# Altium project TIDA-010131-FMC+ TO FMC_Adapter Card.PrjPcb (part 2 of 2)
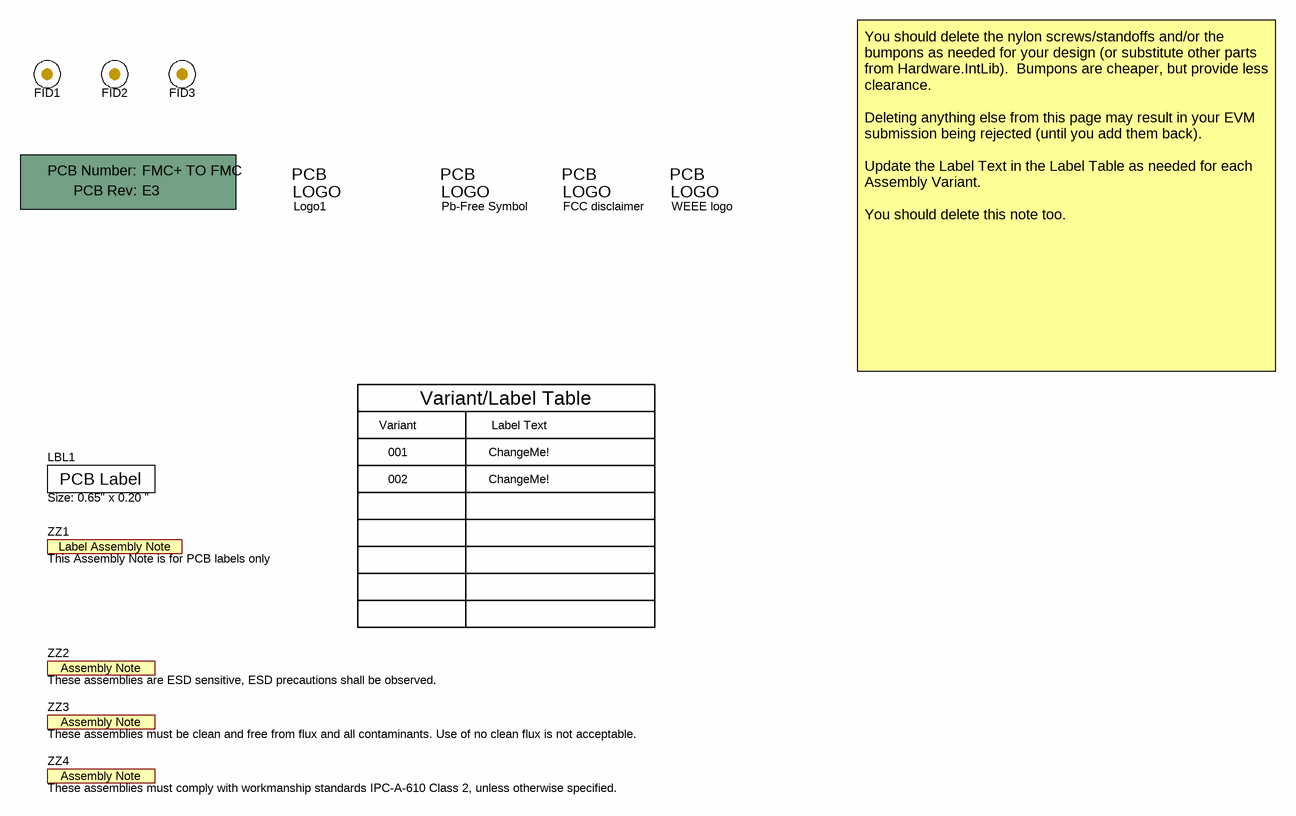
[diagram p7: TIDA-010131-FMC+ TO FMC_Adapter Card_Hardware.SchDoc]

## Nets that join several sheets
GND: TIDA-010131-FMC+ TO FMC_Adapter Card_Sheet1 (33 pins), TIDA-010131-FMC+ TO FMC_Adapter Card_Sheet2 (204 pins), TIDA-010131-FMC+ TO FMC_Adapter Card_Sheet3 (153 pins), TIDA-010131-FMC+ TO FMC_Adapter Card_Sheet4 (203 pins)
ADC_ALT_SYNC_N: TIDA-010131-FMC+ TO FMC_Adapter Card_Sheet2 (J1.H32), TIDA-010131-FMC+ TO FMC_Adapter Card_Sheet3 (R39.1 R45.2)
ADC_ALT_SYNC_P: TIDA-010131-FMC+ TO FMC_Adapter Card_Sheet1 (R27.1), TIDA-010131-FMC+ TO FMC_Adapter Card_Sheet2 (J1.H31), TIDA-010131-FMC+ TO FMC_Adapter Card_Sheet3 (R19.1)
ADC_DA0_N: TIDA-010131-FMC+ TO FMC_Adapter Card_Sheet2 (J1.C7), TIDA-010131-FMC+ TO FMC_Adapter Card_Sheet3 (J2.C7), TIDA-010131-FMC+ TO FMC_Adapter Card_Sheet4 (J4.C7)
ADC_DA0_P: TIDA-010131-FMC+ TO FMC_Adapter Card_Sheet2 (J1.C6), TIDA-010131-FMC+ TO FMC_Adapter Card_Sheet3 (J2.C6), TIDA-010131-FMC+ TO FMC_Adapter Card_Sheet4 (J4.C6)
ADC_DA1_N: TIDA-010131-FMC+ TO FMC_Adapter Card_Sheet2 (J1.A3), TIDA-010131-FMC+ TO FMC_Adapter Card_Sheet3 (J2.A3), TIDA-010131-FMC+ TO FMC_Adapter Card_Sheet4 (J4.A3)
ADC_DA1_P: TIDA-010131-FMC+ TO FMC_Adapter Card_Sheet2 (J1.A2), TIDA-010131-FMC+ TO FMC_Adapter Card_Sheet3 (J2.A2), TIDA-010131-FMC+ TO FMC_Adapter Card_Sheet4 (J4.A2)
ADC_DA2_N: TIDA-010131-FMC+ TO FMC_Adapter Card_Sheet2 (J1.A7), TIDA-010131-FMC+ TO FMC_Adapter Card_Sheet3 (J2.A7), TIDA-010131-FMC+ TO FMC_Adapter Card_Sheet4 (J4.A7)
ADC_DA2_P: TIDA-010131-FMC+ TO FMC_Adapter Card_Sheet2 (J1.A6), TIDA-010131-FMC+ TO FMC_Adapter Card_Sheet3 (J2.A6), TIDA-010131-FMC+ TO FMC_Adapter Card_Sheet4 (J4.A6)
ADC_DA3_N: TIDA-010131-FMC+ TO FMC_Adapter Card_Sheet2 (J1.A11), TIDA-010131-FMC+ TO FMC_Adapter Card_Sheet3 (J2.A11), TIDA-010131-FMC+ TO FMC_Adapter Card_Sheet4 (J4.A11)
ADC_DA3_P: TIDA-010131-FMC+ TO FMC_Adapter Card_Sheet2 (J1.A10), TIDA-010131-FMC+ TO FMC_Adapter Card_Sheet3 (J2.A10), TIDA-010131-FMC+ TO FMC_Adapter Card_Sheet4 (J4.A10)
ADC_DA4_N: TIDA-010131-FMC+ TO FMC_Adapter Card_Sheet2 (J1.A15), TIDA-010131-FMC+ TO FMC_Adapter Card_Sheet3 (J2.A15), TIDA-010131-FMC+ TO FMC_Adapter Card_Sheet4 (J4.A15)
ADC_DA4_P: TIDA-010131-FMC+ TO FMC_Adapter Card_Sheet2 (J1.A14), TIDA-010131-FMC+ TO FMC_Adapter Card_Sheet3 (J2.A14), TIDA-010131-FMC+ TO FMC_Adapter Card_Sheet4 (J4.A14)
ADC_DA5_N: TIDA-010131-FMC+ TO FMC_Adapter Card_Sheet2 (J1.A19), TIDA-010131-FMC+ TO FMC_Adapter Card_Sheet3 (J2.A19), TIDA-010131-FMC+ TO FMC_Adapter Card_Sheet4 (J4.A19)
ADC_DA5_P: TIDA-010131-FMC+ TO FMC_Adapter Card_Sheet2 (J1.A18), TIDA-010131-FMC+ TO FMC_Adapter Card_Sheet3 (J2.A18), TIDA-010131-FMC+ TO FMC_Adapter Card_Sheet4 (J4.A18)
ADC_DA6_N: TIDA-010131-FMC+ TO FMC_Adapter Card_Sheet2 (J1.B17), TIDA-010131-FMC+ TO FMC_Adapter Card_Sheet3 (J2.B17), TIDA-010131-FMC+ TO FMC_Adapter Card_Sheet4 (J4.B17)
ADC_DA6_P: TIDA-010131-FMC+ TO FMC_Adapter Card_Sheet2 (J1.B16), TIDA-010131-FMC+ TO FMC_Adapter Card_Sheet3 (J2.B16), TIDA-010131-FMC+ TO FMC_Adapter Card_Sheet4 (J4.B16)
ADC_DA7_N: TIDA-010131-FMC+ TO FMC_Adapter Card_Sheet2 (J1.B13), TIDA-010131-FMC+ TO FMC_Adapter Card_Sheet3 (J2.B13), TIDA-010131-FMC+ TO FMC_Adapter Card_Sheet4 (J4.B13)
ADC_DA7_P: TIDA-010131-FMC+ TO FMC_Adapter Card_Sheet2 (J1.B12), TIDA-010131-FMC+ TO FMC_Adapter Card_Sheet3 (J2.B12), TIDA-010131-FMC+ TO FMC_Adapter Card_Sheet4 (J4.B12)
ADC_DB0_N: TIDA-010131-FMC+ TO FMC_Adapter Card_Sheet2 (J1.B5), TIDA-010131-FMC+ TO FMC_Adapter Card_Sheet3 (J2.B5), TIDA-010131-FMC+ TO FMC_Adapter Card_Sheet4 (J4.B5)
ADC_DB0_P: TIDA-010131-FMC+ TO FMC_Adapter Card_Sheet2 (J1.B4), TIDA-010131-FMC+ TO FMC_Adapter Card_Sheet3 (J2.B4), TIDA-010131-FMC+ TO FMC_Adapter Card_Sheet4 (J4.B4)
ADC_DB1_N: TIDA-010131-FMC+ TO FMC_Adapter Card_Sheet2 (J1.B9), TIDA-010131-FMC+ TO FMC_Adapter Card_Sheet3 (J2.B9), TIDA-010131-FMC+ TO FMC_Adapter Card_Sheet4 (J4.B9)
ADC_DB1_P: TIDA-010131-FMC+ TO FMC_Adapter Card_Sheet2 (J1.B8), TIDA-010131-FMC+ TO FMC_Adapter Card_Sheet3 (J2.B8), TIDA-010131-FMC+ TO FMC_Adapter Card_Sheet4 (J4.B8)
ADC_DB2_N: TIDA-010131-FMC+ TO FMC_Adapter Card_Sheet2 (J1.Y11), TIDA-010131-FMC+ TO FMC_Adapter Card_Sheet4 (J4.Y11)
ADC_DB2_P: TIDA-010131-FMC+ TO FMC_Adapter Card_Sheet2 (J1.Y10), TIDA-010131-FMC+ TO FMC_Adapter Card_Sheet4 (J4.Y10)
ADC_DB3_N: TIDA-010131-FMC+ TO FMC_Adapter Card_Sheet2 (J1.Y15), TIDA-010131-FMC+ TO FMC_Adapter Card_Sheet4 (J4.Y15)
ADC_DB3_P: TIDA-010131-FMC+ TO FMC_Adapter Card_Sheet2 (J1.Y14), TIDA-010131-FMC+ TO FMC_Adapter Card_Sheet4 (J4.Y14)
ADC_DB4_N: TIDA-010131-FMC+ TO FMC_Adapter Card_Sheet2 (J1.Y19), TIDA-010131-FMC+ TO FMC_Adapter Card_Sheet4 (J4.Y19)
ADC_DB4_P: TIDA-010131-FMC+ TO FMC_Adapter Card_Sheet2 (J1.Y18), TIDA-010131-FMC+ TO FMC_Adapter Card_Sheet4 (J4.Y18)
ADC_DB5_N: TIDA-010131-FMC+ TO FMC_Adapter Card_Sheet2 (J1.Y23), TIDA-010131-FMC+ TO FMC_Adapter Card_Sheet4 (J4.Y23)
ADC_DB5_P: TIDA-010131-FMC+ TO FMC_Adapter Card_Sheet2 (J1.Y22), TIDA-010131-FMC+ TO FMC_Adapter Card_Sheet4 (J4.Y22)
ADC_DB6_N: TIDA-010131-FMC+ TO FMC_Adapter Card_Sheet2 (J1.Z13), TIDA-010131-FMC+ TO FMC_Adapter Card_Sheet4 (J4.Z13)
ADC_DB6_P: TIDA-010131-FMC+ TO FMC_Adapter Card_Sheet2 (J1.Z12), TIDA-010131-FMC+ TO FMC_Adapter Card_Sheet4 (J4.Z12)
ADC_DB7_N: TIDA-010131-FMC+ TO FMC_Adapter Card_Sheet2 (J1.Z17), TIDA-010131-FMC+ TO FMC_Adapter Card_Sheet4 (J4.Z17)
ADC_DB7_P: TIDA-010131-FMC+ TO FMC_Adapter Card_Sheet2 (J1.Z16), TIDA-010131-FMC+ TO FMC_Adapter Card_Sheet4 (J4.Z16)
ADC_SYNC_N: TIDA-010131-FMC+ TO FMC_Adapter Card_Sheet2 (R48.2), TIDA-010131-FMC+ TO FMC_Adapter Card_Sheet3 (J2.G13), TIDA-010131-FMC+ TO FMC_Adapter Card_Sheet4 (J4.G13)
ADC_SYNC_P: TIDA-010131-FMC+ TO FMC_Adapter Card_Sheet2 (R47.2), TIDA-010131-FMC+ TO FMC_Adapter Card_Sheet3 (J2.G12), TIDA-010131-FMC+ TO FMC_Adapter Card_Sheet4 (J4.G12)
C18: TIDA-010131-FMC+ TO FMC_Adapter Card_Sheet2 (J1.C18), TIDA-010131-FMC+ TO FMC_Adapter Card_Sheet3 (J2.C18), TIDA-010131-FMC+ TO FMC_Adapter Card_Sheet4 (J4.C18)
C34: TIDA-010131-FMC+ TO FMC_Adapter Card_Sheet2 (J1.C34), TIDA-010131-FMC+ TO FMC_Adapter Card_Sheet3 (J2.C34), TIDA-010131-FMC+ TO FMC_Adapter Card_Sheet4 (J4.C34)
C35: TIDA-010131-FMC+ TO FMC_Adapter Card_Sheet2 (J1.C35), TIDA-010131-FMC+ TO FMC_Adapter Card_Sheet3 (J2.C35), TIDA-010131-FMC+ TO FMC_Adapter Card_Sheet4 (J4.C35)
C37: TIDA-010131-FMC+ TO FMC_Adapter Card_Sheet2 (J1.C37), TIDA-010131-FMC+ TO FMC_Adapter Card_Sheet3 (J2.C37), TIDA-010131-FMC+ TO FMC_Adapter Card_Sheet4 (J4.C37)
C39: TIDA-010131-FMC+ TO FMC_Adapter Card_Sheet2 (J1.C39), TIDA-010131-FMC+ TO FMC_Adapter Card_Sheet3 (J2.C39), TIDA-010131-FMC+ TO FMC_Adapter Card_Sheet4 (J4.C39)
D1: TIDA-010131-FMC+ TO FMC_Adapter Card_Sheet2 (J1.D1), TIDA-010131-FMC+ TO FMC_Adapter Card_Sheet3 (J2.D1), TIDA-010131-FMC+ TO FMC_Adapter Card_Sheet4 (J4.D1)
D17: TIDA-010131-FMC+ TO FMC_Adapter Card_Sheet2 (J1.D17), TIDA-010131-FMC+ TO FMC_Adapter Card_Sheet3 (J2.D17), TIDA-010131-FMC+ TO FMC_Adapter Card_Sheet4 (J4.D17)
D18: TIDA-010131-FMC+ TO FMC_Adapter Card_Sheet2 (J1.D18), TIDA-010131-FMC+ TO FMC_Adapter Card_Sheet3 (J2.D18), TIDA-010131-FMC+ TO FMC_Adapter Card_Sheet4 (J4.D18)
D32: TIDA-010131-FMC+ TO FMC_Adapter Card_Sheet2 (J1.D32), TIDA-010131-FMC+ TO FMC_Adapter Card_Sheet3 (J2.D32), TIDA-010131-FMC+ TO FMC_Adapter Card_Sheet4 (J4.D32)
D35: TIDA-010131-FMC+ TO FMC_Adapter Card_Sheet2 (J1.D35), TIDA-010131-FMC+ TO FMC_Adapter Card_Sheet3 (J2.D35), TIDA-010131-FMC+ TO FMC_Adapter Card_Sheet4 (J4.D35)
D36: TIDA-010131-FMC+ TO FMC_Adapter Card_Sheet2 (J1.D36), TIDA-010131-FMC+ TO FMC_Adapter Card_Sheet3 (J2.D36), TIDA-010131-FMC+ TO FMC_Adapter Card_Sheet4 (J4.D36)
D38: TIDA-010131-FMC+ TO FMC_Adapter Card_Sheet2 (J1.D38), TIDA-010131-FMC+ TO FMC_Adapter Card_Sheet3 (J2.D38), TIDA-010131-FMC+ TO FMC_Adapter Card_Sheet4 (J4.D38)
D40: TIDA-010131-FMC+ TO FMC_Adapter Card_Sheet2 (J1.D40), TIDA-010131-FMC+ TO FMC_Adapter Card_Sheet3 (J2.D40), TIDA-010131-FMC+ TO FMC_Adapter Card_Sheet4 (J4.D40)
DAC_ALT_SYNC_N: TIDA-010131-FMC+ TO FMC_Adapter Card_Sheet2 (J1.F20), TIDA-010131-FMC+ TO FMC_Adapter Card_Sheet3 (J2.F20), TIDA-010131-FMC+ TO FMC_Adapter Card_Sheet4 (J4.F20)
DAC_ALT_SYNC_P: TIDA-010131-FMC+ TO FMC_Adapter Card_Sheet2 (J1.F19), TIDA-010131-FMC+ TO FMC_Adapter Card_Sheet3 (J2.F19), TIDA-010131-FMC+ TO FMC_Adapter Card_Sheet4 (J4.F19)
DAC_DA0_N: TIDA-010131-FMC+ TO FMC_Adapter Card_Sheet2 (J1.C3), TIDA-010131-FMC+ TO FMC_Adapter Card_Sheet3 (J2.C3), TIDA-010131-FMC+ TO FMC_Adapter Card_Sheet4 (J4.C3)
DAC_DA0_P: TIDA-010131-FMC+ TO FMC_Adapter Card_Sheet2 (J1.C2), TIDA-010131-FMC+ TO FMC_Adapter Card_Sheet3 (J2.C2), TIDA-010131-FMC+ TO FMC_Adapter Card_Sheet4 (J4.C2)
DAC_DA1_N: TIDA-010131-FMC+ TO FMC_Adapter Card_Sheet2 (J1.A23), TIDA-010131-FMC+ TO FMC_Adapter Card_Sheet3 (J2.A23), TIDA-010131-FMC+ TO FMC_Adapter Card_Sheet4 (J4.A23)
DAC_DA1_P: TIDA-010131-FMC+ TO FMC_Adapter Card_Sheet2 (J1.A22), TIDA-010131-FMC+ TO FMC_Adapter Card_Sheet3 (J2.A22), TIDA-010131-FMC+ TO FMC_Adapter Card_Sheet4 (J4.A22)
DAC_DA2_N: TIDA-010131-FMC+ TO FMC_Adapter Card_Sheet2 (J1.A27), TIDA-010131-FMC+ TO FMC_Adapter Card_Sheet3 (J2.A27), TIDA-010131-FMC+ TO FMC_Adapter Card_Sheet4 (J4.A27)
DAC_DA2_P: TIDA-010131-FMC+ TO FMC_Adapter Card_Sheet2 (J1.A26), TIDA-010131-FMC+ TO FMC_Adapter Card_Sheet3 (J2.A26), TIDA-010131-FMC+ TO FMC_Adapter Card_Sheet4 (J4.A26)
DAC_DA3_N: TIDA-010131-FMC+ TO FMC_Adapter Card_Sheet2 (J1.A31), TIDA-010131-FMC+ TO FMC_Adapter Card_Sheet3 (J2.A31), TIDA-010131-FMC+ TO FMC_Adapter Card_Sheet4 (J4.A31)
DAC_DA3_P: TIDA-010131-FMC+ TO FMC_Adapter Card_Sheet2 (J1.A30), TIDA-010131-FMC+ TO FMC_Adapter Card_Sheet3 (J2.A30), TIDA-010131-FMC+ TO FMC_Adapter Card_Sheet4 (J4.A30)
DAC_DA4_N: TIDA-010131-FMC+ TO FMC_Adapter Card_Sheet2 (J1.A35), TIDA-010131-FMC+ TO FMC_Adapter Card_Sheet3 (J2.A35), TIDA-010131-FMC+ TO FMC_Adapter Card_Sheet4 (J4.A35)
DAC_DA4_P: TIDA-010131-FMC+ TO FMC_Adapter Card_Sheet2 (J1.A34), TIDA-010131-FMC+ TO FMC_Adapter Card_Sheet3 (J2.A34), TIDA-010131-FMC+ TO FMC_Adapter Card_Sheet4 (J4.A34)
DAC_DA5_N: TIDA-010131-FMC+ TO FMC_Adapter Card_Sheet2 (J1.A39), TIDA-010131-FMC+ TO FMC_Adapter Card_Sheet3 (J2.A39), TIDA-010131-FMC+ TO FMC_Adapter Card_Sheet4 (J4.A39)
DAC_DA5_P: TIDA-010131-FMC+ TO FMC_Adapter Card_Sheet2 (J1.A38), TIDA-010131-FMC+ TO FMC_Adapter Card_Sheet3 (J2.A38), TIDA-010131-FMC+ TO FMC_Adapter Card_Sheet4 (J4.A38)
DAC_DA6_N: TIDA-010131-FMC+ TO FMC_Adapter Card_Sheet2 (J1.B37), TIDA-010131-FMC+ TO FMC_Adapter Card_Sheet3 (J2.B37), TIDA-010131-FMC+ TO FMC_Adapter Card_Sheet4 (J4.B37)
DAC_DA6_P: TIDA-010131-FMC+ TO FMC_Adapter Card_Sheet2 (J1.B36), TIDA-010131-FMC+ TO FMC_Adapter Card_Sheet3 (J2.B36), TIDA-010131-FMC+ TO FMC_Adapter Card_Sheet4 (J4.B36)
DAC_DA7_N: TIDA-010131-FMC+ TO FMC_Adapter Card_Sheet2 (J1.B33), TIDA-010131-FMC+ TO FMC_Adapter Card_Sheet3 (J2.B33), TIDA-010131-FMC+ TO FMC_Adapter Card_Sheet4 (J4.B33)
DAC_DA7_P: TIDA-010131-FMC+ TO FMC_Adapter Card_Sheet2 (J1.B32), TIDA-010131-FMC+ TO FMC_Adapter Card_Sheet3 (J2.B32), TIDA-010131-FMC+ TO FMC_Adapter Card_Sheet4 (J4.B32)
DAC_DB0_N: TIDA-010131-FMC+ TO FMC_Adapter Card_Sheet2 (J1.B25), TIDA-010131-FMC+ TO FMC_Adapter Card_Sheet3 (J2.B25), TIDA-010131-FMC+ TO FMC_Adapter Card_Sheet4 (J4.B25)
DAC_DB0_P: TIDA-010131-FMC+ TO FMC_Adapter Card_Sheet2 (J1.B24), TIDA-010131-FMC+ TO FMC_Adapter Card_Sheet3 (J2.B24), TIDA-010131-FMC+ TO FMC_Adapter Card_Sheet4 (J4.B24)
DAC_DB1_N: TIDA-010131-FMC+ TO FMC_Adapter Card_Sheet2 (J1.B29), TIDA-010131-FMC+ TO FMC_Adapter Card_Sheet3 (J2.B29), TIDA-010131-FMC+ TO FMC_Adapter Card_Sheet4 (J4.B29)
DAC_DB1_P: TIDA-010131-FMC+ TO FMC_Adapter Card_Sheet2 (J1.B28), TIDA-010131-FMC+ TO FMC_Adapter Card_Sheet3 (J2.B28), TIDA-010131-FMC+ TO FMC_Adapter Card_Sheet4 (J4.B28)
DAC_DB2_N: TIDA-010131-FMC+ TO FMC_Adapter Card_Sheet2 (J1.Y7), TIDA-010131-FMC+ TO FMC_Adapter Card_Sheet4 (J4.Y7)
DAC_DB2_P: TIDA-010131-FMC+ TO FMC_Adapter Card_Sheet2 (J1.Y6), TIDA-010131-FMC+ TO FMC_Adapter Card_Sheet4 (J4.Y6)
DAC_DB3_N: TIDA-010131-FMC+ TO FMC_Adapter Card_Sheet2 (J1.Y27), TIDA-010131-FMC+ TO FMC_Adapter Card_Sheet4 (J4.Y27)
DAC_DB3_P: TIDA-010131-FMC+ TO FMC_Adapter Card_Sheet2 (J1.Y26), TIDA-010131-FMC+ TO FMC_Adapter Card_Sheet4 (J4.Y26)
DAC_DB4_N: TIDA-010131-FMC+ TO FMC_Adapter Card_Sheet2 (J1.Y31), TIDA-010131-FMC+ TO FMC_Adapter Card_Sheet4 (J4.Y31)
DAC_DB4_P: TIDA-010131-FMC+ TO FMC_Adapter Card_Sheet2 (J1.Y30), TIDA-010131-FMC+ TO FMC_Adapter Card_Sheet4 (J4.Y30)
DAC_DB5_N: TIDA-010131-FMC+ TO FMC_Adapter Card_Sheet2 (J1.Z9), TIDA-010131-FMC+ TO FMC_Adapter Card_Sheet4 (J4.Z9)
DAC_DB5_P: TIDA-010131-FMC+ TO FMC_Adapter Card_Sheet2 (J1.Z8), TIDA-010131-FMC+ TO FMC_Adapter Card_Sheet4 (J4.Z8)
DAC_DB6_N: TIDA-010131-FMC+ TO FMC_Adapter Card_Sheet2 (J1.Z25), TIDA-010131-FMC+ TO FMC_Adapter Card_Sheet4 (J4.Z25)
DAC_DB6_P: TIDA-010131-FMC+ TO FMC_Adapter Card_Sheet2 (J1.Z24), TIDA-010131-FMC+ TO FMC_Adapter Card_Sheet4 (J4.Z24)
DAC_DB7_N: TIDA-010131-FMC+ TO FMC_Adapter Card_Sheet2 (J1.Z29), TIDA-010131-FMC+ TO FMC_Adapter Card_Sheet4 (J4.Z29)
DAC_DB7_P: TIDA-010131-FMC+ TO FMC_Adapter Card_Sheet2 (J1.Z28), TIDA-010131-FMC+ TO FMC_Adapter Card_Sheet4 (J4.Z28)
DAC_SYNC_N: TIDA-010131-FMC+ TO FMC_Adapter Card_Sheet2 (J1.F11), TIDA-010131-FMC+ TO FMC_Adapter Card_Sheet3 (J2.F11), TIDA-010131-FMC+ TO FMC_Adapter Card_Sheet4 (J4.F11)
DAC_SYNC_P: TIDA-010131-FMC+ TO FMC_Adapter Card_Sheet2 (J1.F10), TIDA-010131-FMC+ TO FMC_Adapter Card_Sheet3 (J2.F10), TIDA-010131-FMC+ TO FMC_Adapter Card_Sheet4 (J4.F10)
DCLKOUT12_N: TIDA-010131-FMC+ TO FMC_Adapter Card_Sheet1 (R36.2), TIDA-010131-FMC+ TO FMC_Adapter Card_Sheet2 (R18.1), TIDA-010131-FMC+ TO FMC_Adapter Card_Sheet4 (J4.Z21)
DCLKOUT12_P: TIDA-010131-FMC+ TO FMC_Adapter Card_Sheet1 (R37.2), TIDA-010131-FMC+ TO FMC_Adapter Card_Sheet2 (R17.1), TIDA-010131-FMC+ TO FMC_Adapter Card_Sheet4 (J4.Z20)
E39: TIDA-010131-FMC+ TO FMC_Adapter Card_Sheet2 (J1.E39), TIDA-010131-FMC+ TO FMC_Adapter Card_Sheet3 (J2.E39), TIDA-010131-FMC+ TO FMC_Adapter Card_Sheet4 (J4.E39)
F1: TIDA-010131-FMC+ TO FMC_Adapter Card_Sheet2 (J1.F1), TIDA-010131-FMC+ TO FMC_Adapter Card_Sheet3 (J2.F1), TIDA-010131-FMC+ TO FMC_Adapter Card_Sheet4 (J4.F1)
F40: TIDA-010131-FMC+ TO FMC_Adapter Card_Sheet2 (J1.F40), TIDA-010131-FMC+ TO FMC_Adapter Card_Sheet3 (J2.F40), TIDA-010131-FMC+ TO FMC_Adapter Card_Sheet4 (J4.F40)
FMC_DAC_SCLK: TIDA-010131-FMC+ TO FMC_Adapter Card_Sheet2 (J1.C14), TIDA-010131-FMC+ TO FMC_Adapter Card_Sheet3 (J2.C14), TIDA-010131-FMC+ TO FMC_Adapter Card_Sheet4 (J4.C14)
FMC_DAC_SDENB: TIDA-010131-FMC+ TO FMC_Adapter Card_Sheet2 (J1.D15), TIDA-010131-FMC+ TO FMC_Adapter Card_Sheet3 (J2.D15), TIDA-010131-FMC+ TO FMC_Adapter Card_Sheet4 (J4.D15)
FMC_DAC_SDIO: TIDA-010131-FMC+ TO FMC_Adapter Card_Sheet2 (J1.C15), TIDA-010131-FMC+ TO FMC_Adapter Card_Sheet3 (J2.C15), TIDA-010131-FMC+ TO FMC_Adapter Card_Sheet4 (J4.C15)
FMC_DAC_SDO: TIDA-010131-FMC+ TO FMC_Adapter Card_Sheet2 (J1.D14), TIDA-010131-FMC+ TO FMC_Adapter Card_Sheet3 (J2.D14), TIDA-010131-FMC+ TO FMC_Adapter Card_Sheet4 (J4.D14)
FMC_FSPICLKA: TIDA-010131-FMC+ TO FMC_Adapter Card_Sheet2 (J1.J6), TIDA-010131-FMC+ TO FMC_Adapter Card_Sheet3 (J2.J6), TIDA-010131-FMC+ TO FMC_Adapter Card_Sheet4 (J4.J6)
FMC_FSPICLKB: TIDA-010131-FMC+ TO FMC_Adapter Card_Sheet2 (J1.J7), TIDA-010131-FMC+ TO FMC_Adapter Card_Sheet3 (J2.J7), TIDA-010131-FMC+ TO FMC_Adapter Card_Sheet4 (J4.J7)
FMC_FSPICLKC: TIDA-010131-FMC+ TO FMC_Adapter Card_Sheet2 (J1.J9), TIDA-010131-FMC+ TO FMC_Adapter Card_Sheet3 (J2.J9), TIDA-010131-FMC+ TO FMC_Adapter Card_Sheet4 (J4.J9)
FMC_FSPICLKD: TIDA-010131-FMC+ TO FMC_Adapter Card_Sheet2 (J1.J10), TIDA-010131-FMC+ TO FMC_Adapter Card_Sheet3 (J2.J10), TIDA-010131-FMC+ TO FMC_Adapter Card_Sheet4 (J4.J10)
FMC_FSPIDA: TIDA-010131-FMC+ TO FMC_Adapter Card_Sheet2 (J1.J12), TIDA-010131-FMC+ TO FMC_Adapter Card_Sheet3 (J2.J12), TIDA-010131-FMC+ TO FMC_Adapter Card_Sheet4 (J4.J12)
FMC_FSPIDB: TIDA-010131-FMC+ TO FMC_Adapter Card_Sheet2 (J1.J13), TIDA-010131-FMC+ TO FMC_Adapter Card_Sheet3 (J2.J13), TIDA-010131-FMC+ TO FMC_Adapter Card_Sheet4 (J4.J13)
FMC_LMK_CS: TIDA-010131-FMC+ TO FMC_Adapter Card_Sheet2 (J1.H17), TIDA-010131-FMC+ TO FMC_Adapter Card_Sheet3 (J2.H17), TIDA-010131-FMC+ TO FMC_Adapter Card_Sheet4 (J4.H17)
FMC_LMK_SCK: TIDA-010131-FMC+ TO FMC_Adapter Card_Sheet2 (J1.G15), TIDA-010131-FMC+ TO FMC_Adapter Card_Sheet3 (J2.G15), TIDA-010131-FMC+ TO FMC_Adapter Card_Sheet4 (J4.G15)
FMC_LMK_SDIO: TIDA-010131-FMC+ TO FMC_Adapter Card_Sheet2 (J1.G16), TIDA-010131-FMC+ TO FMC_Adapter Card_Sheet3 (J2.G16), TIDA-010131-FMC+ TO FMC_Adapter Card_Sheet4 (J4.G16)
FMC_LMK_SDO: TIDA-010131-FMC+ TO FMC_Adapter Card_Sheet2 (J1.H16), TIDA-010131-FMC+ TO FMC_Adapter Card_Sheet3 (J2.H16), TIDA-010131-FMC+ TO FMC_Adapter Card_Sheet4 (J4.H16)
FMC_RXADSA1PD: TIDA-010131-FMC+ TO FMC_Adapter Card_Sheet2 (J1.K7), TIDA-010131-FMC+ TO FMC_Adapter Card_Sheet3 (J2.K7), TIDA-010131-FMC+ TO FMC_Adapter Card_Sheet4 (J4.K7)
FMC_RXADSA2PD: TIDA-010131-FMC+ TO FMC_Adapter Card_Sheet2 (J1.K8), TIDA-010131-FMC+ TO FMC_Adapter Card_Sheet3 (J2.K8), TIDA-010131-FMC+ TO FMC_Adapter Card_Sheet4 (J4.K8)
FMC_RXADSAFAST: TIDA-010131-FMC+ TO FMC_Adapter Card_Sheet2 (J1.G18), TIDA-010131-FMC+ TO FMC_Adapter Card_Sheet3 (J2.G18), TIDA-010131-FMC+ TO FMC_Adapter Card_Sheet4 (J4.G18)
FMC_RXAPD2H: TIDA-010131-FMC+ TO FMC_Adapter Card_Sheet2 (J1.K10), TIDA-010131-FMC+ TO FMC_Adapter Card_Sheet3 (J2.K10), TIDA-010131-FMC+ TO FMC_Adapter Card_Sheet4 (J4.K10)
FMC_RXAPD2L: TIDA-010131-FMC+ TO FMC_Adapter Card_Sheet2 (J1.K11), TIDA-010131-FMC+ TO FMC_Adapter Card_Sheet3 (J2.K11), TIDA-010131-FMC+ TO FMC_Adapter Card_Sheet4 (J4.K11)
FMC_RXBDSA1PD: TIDA-010131-FMC+ TO FMC_Adapter Card_Sheet2 (J1.K13), TIDA-010131-FMC+ TO FMC_Adapter Card_Sheet3 (J2.K13), TIDA-010131-FMC+ TO FMC_Adapter Card_Sheet4 (J4.K13)
FMC_RXBDSA2PD: TIDA-010131-FMC+ TO FMC_Adapter Card_Sheet2 (J1.K14), TIDA-010131-FMC+ TO FMC_Adapter Card_Sheet3 (J2.K14), TIDA-010131-FMC+ TO FMC_Adapter Card_Sheet4 (J4.K14)
FMC_RXBDSAFAST: TIDA-010131-FMC+ TO FMC_Adapter Card_Sheet2 (J1.G21), TIDA-010131-FMC+ TO FMC_Adapter Card_Sheet3 (J2.G21), TIDA-010131-FMC+ TO FMC_Adapter Card_Sheet4 (J4.G21)
FMC_RXBPD2H: TIDA-010131-FMC+ TO FMC_Adapter Card_Sheet2 (J1.J18), TIDA-010131-FMC+ TO FMC_Adapter Card_Sheet3 (J2.J18), TIDA-010131-FMC+ TO FMC_Adapter Card_Sheet4 (J4.J18)
FMC_RXBPD2L: TIDA-010131-FMC+ TO FMC_Adapter Card_Sheet2 (J1.J19), TIDA-010131-FMC+ TO FMC_Adapter Card_Sheet3 (J2.J19), TIDA-010131-FMC+ TO FMC_Adapter Card_Sheet4 (J4.J19)
FMC_RXDSASW: TIDA-010131-FMC+ TO FMC_Adapter Card_Sheet2 (J1.F13), TIDA-010131-FMC+ TO FMC_Adapter Card_Sheet3 (J2.F13), TIDA-010131-FMC+ TO FMC_Adapter Card_Sheet4 (J4.F13)
FMC_SCL: TIDA-010131-FMC+ TO FMC_Adapter Card_Sheet2 (J1.C30), TIDA-010131-FMC+ TO FMC_Adapter Card_Sheet3 (J2.C30), TIDA-010131-FMC+ TO FMC_Adapter Card_Sheet4 (J4.C30)
FMC_SDA: TIDA-010131-FMC+ TO FMC_Adapter Card_Sheet2 (J1.C31), TIDA-010131-FMC+ TO FMC_Adapter Card_Sheet3 (J2.C31), TIDA-010131-FMC+ TO FMC_Adapter Card_Sheet4 (J4.C31)
FMC_SPIACLK: TIDA-010131-FMC+ TO FMC_Adapter Card_Sheet2 (J1.D11), TIDA-010131-FMC+ TO FMC_Adapter Card_Sheet3 (J2.D11), TIDA-010131-FMC+ TO FMC_Adapter Card_Sheet4 (J4.D11)
FMC_SPIASDIO: TIDA-010131-FMC+ TO FMC_Adapter Card_Sheet2 (J1.D12), TIDA-010131-FMC+ TO FMC_Adapter Card_Sheet3 (J2.D12), TIDA-010131-FMC+ TO FMC_Adapter Card_Sheet4 (J4.D12)
FMC_SPIASDO: TIDA-010131-FMC+ TO FMC_Adapter Card_Sheet2 (J1.D26), TIDA-010131-FMC+ TO FMC_Adapter Card_Sheet3 (J2.D26), TIDA-010131-FMC+ TO FMC_Adapter Card_Sheet4 (J4.D26)
FMC_SPIASEN: TIDA-010131-FMC+ TO FMC_Adapter Card_Sheet2 (J1.D27), TIDA-010131-FMC+ TO FMC_Adapter Card_Sheet3 (J2.D27), TIDA-010131-FMC+ TO FMC_Adapter Card_Sheet4 (J4.D27)
FMC_SPIBCLK: TIDA-010131-FMC+ TO FMC_Adapter Card_Sheet2 (J1.E12), TIDA-010131-FMC+ TO FMC_Adapter Card_Sheet3 (J2.E12), TIDA-010131-FMC+ TO FMC_Adapter Card_Sheet4 (J4.E12)
FMC_SPIBSDIO: TIDA-010131-FMC+ TO FMC_Adapter Card_Sheet2 (J1.E13), TIDA-010131-FMC+ TO FMC_Adapter Card_Sheet3 (J2.E13), TIDA-010131-FMC+ TO FMC_Adapter Card_Sheet4 (J4.E13)
FMC_SPIBSDO: TIDA-010131-FMC+ TO FMC_Adapter Card_Sheet2 (J1.E15), TIDA-010131-FMC+ TO FMC_Adapter Card_Sheet3 (J2.E15), TIDA-010131-FMC+ TO FMC_Adapter Card_Sheet4 (J4.E15)
FMC_SPIBSEN: TIDA-010131-FMC+ TO FMC_Adapter Card_Sheet2 (J1.E16), TIDA-010131-FMC+ TO FMC_Adapter Card_Sheet3 (J2.E16), TIDA-010131-FMC+ TO FMC_Adapter Card_Sheet4 (J4.E16)
FMC_TCK: TIDA-010131-FMC+ TO FMC_Adapter Card_Sheet2 (J1.D29), TIDA-010131-FMC+ TO FMC_Adapter Card_Sheet3 (J2.D29), TIDA-010131-FMC+ TO FMC_Adapter Card_Sheet4 (J4.D29)
FMC_TDI: TIDA-010131-FMC+ TO FMC_Adapter Card_Sheet2 (J1.D30), TIDA-010131-FMC+ TO FMC_Adapter Card_Sheet3 (J2.D30), TIDA-010131-FMC+ TO FMC_Adapter Card_Sheet4 (J4.D30)
FMC_TDO: TIDA-010131-FMC+ TO FMC_Adapter Card_Sheet2 (J1.D31), TIDA-010131-FMC+ TO FMC_Adapter Card_Sheet3 (J2.D31), TIDA-010131-FMC+ TO FMC_Adapter Card_Sheet4 (J4.D31)
FMC_TMS: TIDA-010131-FMC+ TO FMC_Adapter Card_Sheet2 (J1.D33), TIDA-010131-FMC+ TO FMC_Adapter Card_Sheet3 (J2.D33), TIDA-010131-FMC+ TO FMC_Adapter Card_Sheet4 (J4.D33)
FMC_TRSTB: TIDA-010131-FMC+ TO FMC_Adapter Card_Sheet2 (J1.D34), TIDA-010131-FMC+ TO FMC_Adapter Card_Sheet3 (J2.D34), TIDA-010131-FMC+ TO FMC_Adapter Card_Sheet4 (J4.D34)
FMC_TXDSASW: TIDA-010131-FMC+ TO FMC_Adapter Card_Sheet2 (J1.F14), TIDA-010131-FMC+ TO FMC_Adapter Card_Sheet3 (J2.F14), TIDA-010131-FMC+ TO FMC_Adapter Card_Sheet4 (J4.F14)
FMC_TXTDD1: TIDA-010131-FMC+ TO FMC_Adapter Card_Sheet2 (J1.F16), TIDA-010131-FMC+ TO FMC_Adapter Card_Sheet3 (J2.F16), TIDA-010131-FMC+ TO FMC_Adapter Card_Sheet4 (J4.F16)
FMC_TXTDD2: TIDA-010131-FMC+ TO FMC_Adapter Card_Sheet2 (J1.F17), TIDA-010131-FMC+ TO FMC_Adapter Card_Sheet3 (J2.F17), TIDA-010131-FMC+ TO FMC_Adapter Card_Sheet4 (J4.F17)
FPGA_CLK1_N: TIDA-010131-FMC+ TO FMC_Adapter Card_Sheet1 (R34.2), TIDA-010131-FMC+ TO FMC_Adapter Card_Sheet2 (R16.1), TIDA-010131-FMC+ TO FMC_Adapter Card_Sheet3 (J2.K5), TIDA-010131-FMC+ TO FMC_Adapter Card_Sheet4 (J4.K5)
FPGA_CLK1_P: TIDA-010131-FMC+ TO FMC_Adapter Card_Sheet1 (R35.2), TIDA-010131-FMC+ TO FMC_Adapter Card_Sheet2 (R14.1), TIDA-010131-FMC+ TO FMC_Adapter Card_Sheet3 (J2.K4), TIDA-010131-FMC+ TO FMC_Adapter Card_Sheet4 (J4.K4)
FPGA_CLK2_N: TIDA-010131-FMC+ TO FMC_Adapter Card_Sheet1 (R42.2), TIDA-010131-FMC+ TO FMC_Adapter Card_Sheet2 (R44.2), TIDA-010131-FMC+ TO FMC_Adapter Card_Sheet3 (J2.J3), TIDA-010131-FMC+ TO FMC_Adapter Card_Sheet4 (J4.J3)
FPGA_CLK2_P: TIDA-010131-FMC+ TO FMC_Adapter Card_Sheet1 (R41.2), TIDA-010131-FMC+ TO FMC_Adapter Card_Sheet2 (R43.2), TIDA-010131-FMC+ TO FMC_Adapter Card_Sheet3 (J2.J2), TIDA-010131-FMC+ TO FMC_Adapter Card_Sheet4 (J4.J2)
FPGA_JESD_CLK_A_N: TIDA-010131-FMC+ TO FMC_Adapter Card_Sheet1 (R20.1), TIDA-010131-FMC+ TO FMC_Adapter Card_Sheet2 (R2.1), TIDA-010131-FMC+ TO FMC_Adapter Card_Sheet3 (J2.D5), TIDA-010131-FMC+ TO FMC_Adapter Card_Sheet4 (J4.D5)
FPGA_JESD_CLK_A_P: TIDA-010131-FMC+ TO FMC_Adapter Card_Sheet1 (R22.1), TIDA-010131-FMC+ TO FMC_Adapter Card_Sheet2 (R1.1), TIDA-010131-FMC+ TO FMC_Adapter Card_Sheet3 (J2.D4), TIDA-010131-FMC+ TO FMC_Adapter Card_Sheet4 (J4.D4)
FPGA_JESD_CLK_B_N: TIDA-010131-FMC+ TO FMC_Adapter Card_Sheet1 (R24.1), TIDA-010131-FMC+ TO FMC_Adapter Card_Sheet2 (R4.2), TIDA-010131-FMC+ TO FMC_Adapter Card_Sheet3 (J2.G7), TIDA-010131-FMC+ TO FMC_Adapter Card_Sheet4 (J4.G7)
FPGA_JESD_CLK_B_P: TIDA-010131-FMC+ TO FMC_Adapter Card_Sheet1 (R26.1), TIDA-010131-FMC+ TO FMC_Adapter Card_Sheet2 (R3.2), TIDA-010131-FMC+ TO FMC_Adapter Card_Sheet3 (J2.G6), TIDA-010131-FMC+ TO FMC_Adapter Card_Sheet4 (J4.G6)
FPGA_JESD_CLK_C_N: TIDA-010131-FMC+ TO FMC_Adapter Card_Sheet1 (R30.2), TIDA-010131-FMC+ TO FMC_Adapter Card_Sheet2 (R12.2), TIDA-010131-FMC+ TO FMC_Adapter Card_Sheet3 (J2.G3), TIDA-010131-FMC+ TO FMC_Adapter Card_Sheet4 (J4.G3)
FPGA_JESD_CLK_C_P: TIDA-010131-FMC+ TO FMC_Adapter Card_Sheet1 (R31.2), TIDA-010131-FMC+ TO FMC_Adapter Card_Sheet2 (R11.2), TIDA-010131-FMC+ TO FMC_Adapter Card_Sheet3 (J2.G2), TIDA-010131-FMC+ TO FMC_Adapter Card_Sheet4 (J4.G2)
FPGA_JESD_CLK_D_N: TIDA-010131-FMC+ TO FMC_Adapter Card_Sheet1 (R32.2), TIDA-010131-FMC+ TO FMC_Adapter Card_Sheet2 (R15.1), TIDA-010131-FMC+ TO FMC_Adapter Card_Sheet3 (J2.H5), TIDA-010131-FMC+ TO FMC_Adapter Card_Sheet4 (J4.H5)
FPGA_JESD_CLK_D_P: TIDA-010131-FMC+ TO FMC_Adapter Card_Sheet1 (R33.2), TIDA-010131-FMC+ TO FMC_Adapter Card_Sheet2 (R13.1), TIDA-010131-FMC+ TO FMC_Adapter Card_Sheet3 (J2.H4), TIDA-010131-FMC+ TO FMC_Adapter Card_Sheet4 (J4.H4)
FPGA_JESD_SYSREFM: TIDA-010131-FMC+ TO FMC_Adapter Card_Sheet1 (R21.1), TIDA-010131-FMC+ TO FMC_Adapter Card_Sheet2 (R6.2), TIDA-010131-FMC+ TO FMC_Adapter Card_Sheet3 (J2.G10), TIDA-010131-FMC+ TO FMC_Adapter Card_Sheet4 (J4.G10)
FPGA_JESD_SYSREFP: TIDA-010131-FMC+ TO FMC_Adapter Card_Sheet1 (R23.1), TIDA-010131-FMC+ TO FMC_Adapter Card_Sheet2 (R5.2), TIDA-010131-FMC+ TO FMC_Adapter Card_Sheet3 (J2.G9), TIDA-010131-FMC+ TO FMC_Adapter Card_Sheet4 (J4.G9)
G39: TIDA-010131-FMC+ TO FMC_Adapter Card_Sheet2 (J1.G39), TIDA-010131-FMC+ TO FMC_Adapter Card_Sheet3 (J2.G39), TIDA-010131-FMC+ TO FMC_Adapter Card_Sheet4 (J4.G39)
GBTCLK1_M2C_N: TIDA-010131-FMC+ TO FMC_Adapter Card_Sheet1 (R28.2), TIDA-010131-FMC+ TO FMC_Adapter Card_Sheet2 (R10.1), TIDA-010131-FMC+ TO FMC_Adapter Card_Sheet3 (J2.B21), TIDA-010131-FMC+ TO FMC_Adapter Card_Sheet4 (J4.B21)
GBTCLK1_M2C_P: TIDA-010131-FMC+ TO FMC_Adapter Card_Sheet1 (R29.2), TIDA-010131-FMC+ TO FMC_Adapter Card_Sheet2 (R9.1), TIDA-010131-FMC+ TO FMC_Adapter Card_Sheet3 (J2.B20), TIDA-010131-FMC+ TO FMC_Adapter Card_Sheet4 (J4.B20)
GPIO0: TIDA-010131-FMC+ TO FMC_Adapter Card_Sheet2 (J1.H28), TIDA-010131-FMC+ TO FMC_Adapter Card_Sheet3 (J2.H28), TIDA-010131-FMC+ TO FMC_Adapter Card_Sheet4 (J4.H28)
GPIO1: TIDA-010131-FMC+ TO FMC_Adapter Card_Sheet2 (J1.H29), TIDA-010131-FMC+ TO FMC_Adapter Card_Sheet3 (J2.H29), TIDA-010131-FMC+ TO FMC_Adapter Card_Sheet4 (J4.H29)
H1: TIDA-010131-FMC+ TO FMC_Adapter Card_Sheet2 (J1.H1), TIDA-010131-FMC+ TO FMC_Adapter Card_Sheet3 (J2.H1), TIDA-010131-FMC+ TO FMC_Adapter Card_Sheet4 (J4.H1)
H2: TIDA-010131-FMC+ TO FMC_Adapter Card_Sheet2 (J1.H2), TIDA-010131-FMC+ TO FMC_Adapter Card_Sheet3 (J2.H2), TIDA-010131-FMC+ TO FMC_Adapter Card_Sheet4 (J4.H2)
H40: TIDA-010131-FMC+ TO FMC_Adapter Card_Sheet2 (J1.H40), TIDA-010131-FMC+ TO FMC_Adapter Card_Sheet3 (J2.H40), TIDA-010131-FMC+ TO FMC_Adapter Card_Sheet4 (J4.H40)
J39: TIDA-010131-FMC+ TO FMC_Adapter Card_Sheet2 (J1.J39), TIDA-010131-FMC+ TO FMC_Adapter Card_Sheet3 (J2.J39), TIDA-010131-FMC+ TO FMC_Adapter Card_Sheet4 (J4.J39)
K1: TIDA-010131-FMC+ TO FMC_Adapter Card_Sheet2 (J1.K1), TIDA-010131-FMC+ TO FMC_Adapter Card_Sheet3 (J2.K1), TIDA-010131-FMC+ TO FMC_Adapter Card_Sheet4 (J4.K1)
K40: TIDA-010131-FMC+ TO FMC_Adapter Card_Sheet2 (J1.K40), TIDA-010131-FMC+ TO FMC_Adapter Card_Sheet3 (J2.K40), TIDA-010131-FMC+ TO FMC_Adapter Card_Sheet4 (J4.K40)
LMK04828_RESET/FMC_FSPIDD: TIDA-010131-FMC+ TO FMC_Adapter Card_Sheet1 (R40.1), TIDA-010131-FMC+ TO FMC_Adapter Card_Sheet2 (R38.2), TIDA-010131-FMC+ TO FMC_Adapter Card_Sheet3 (J2.J16), TIDA-010131-FMC+ TO FMC_Adapter Card_Sheet4 (J4.J16)
LMK04828_SYNC/FMC_FSPIDC: TIDA-010131-FMC+ TO FMC_Adapter Card_Sheet1 (R8.1), TIDA-010131-FMC+ TO FMC_Adapter Card_Sheet2 (R7.2), TIDA-010131-FMC+ TO FMC_Adapter Card_Sheet3 (J2.J15), TIDA-010131-FMC+ TO FMC_Adapter Card_Sheet4 (J4.J15)
NB7_RESET: TIDA-010131-FMC+ TO FMC_Adapter Card_Sheet2 (J1.H19), TIDA-010131-FMC+ TO FMC_Adapter Card_Sheet3 (J2.H19), TIDA-010131-FMC+ TO FMC_Adapter Card_Sheet4 (J4.H19)
OVRA0: TIDA-010131-FMC+ TO FMC_Adapter Card_Sheet2 (J1.G27), TIDA-010131-FMC+ TO FMC_Adapter Card_Sheet3 (J2.G27), TIDA-010131-FMC+ TO FMC_Adapter Card_Sheet4 (J4.G27)
SYNC_SE_IN: TIDA-010131-FMC+ TO FMC_Adapter Card_Sheet1 (R25.1), TIDA-010131-FMC+ TO FMC_Adapter Card_Sheet3 (J2.H31 R19.2), TIDA-010131-FMC+ TO FMC_Adapter Card_Sheet4 (J4.H31)
SYNC_SE_IN_N: TIDA-010131-FMC+ TO FMC_Adapter Card_Sheet3 (J2.H32 R39.2 R46.2), TIDA-010131-FMC+ TO FMC_Adapter Card_Sheet4 (J4.H32)
syncb0cmos: TIDA-010131-FMC+ TO FMC_Adapter Card_Sheet2 (J1.E6), TIDA-010131-FMC+ TO FMC_Adapter Card_Sheet3 (J2.E6), TIDA-010131-FMC+ TO FMC_Adapter Card_Sheet4 (J4.E6)
syncb1cmos: TIDA-010131-FMC+ TO FMC_Adapter Card_Sheet2 (J1.E7), TIDA-010131-FMC+ TO FMC_Adapter Card_Sheet3 (J2.E7), TIDA-010131-FMC+ TO FMC_Adapter Card_Sheet4 (J4.E7)
syncb2cmos: TIDA-010131-FMC+ TO FMC_Adapter Card_Sheet2 (J1.E9), TIDA-010131-FMC+ TO FMC_Adapter Card_Sheet3 (J2.E9), TIDA-010131-FMC+ TO FMC_Adapter Card_Sheet4 (J4.E9)
syncb3cmos: TIDA-010131-FMC+ TO FMC_Adapter Card_Sheet2 (J1.E10), TIDA-010131-FMC+ TO FMC_Adapter Card_Sheet3 (J2.E10), TIDA-010131-FMC+ TO FMC_Adapter Card_Sheet4 (J4.E10)
Z1: TIDA-010131-FMC+ TO FMC_Adapter Card_Sheet2 (J1.Z1), TIDA-010131-FMC+ TO FMC_Adapter Card_Sheet4 (J4.Z1)

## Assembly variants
001: not fitted FID1 FID2 FID3 R1 R2 R3 R4 R5 R6 R8 R25 R27 R28 R29 R30 R31 R32 R33 R34 R35 R36 R37 R40 R41 R42 R45 R46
